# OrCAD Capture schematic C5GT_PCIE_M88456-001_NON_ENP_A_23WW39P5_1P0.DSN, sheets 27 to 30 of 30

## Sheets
27 Power 5 - 1.5V: size B
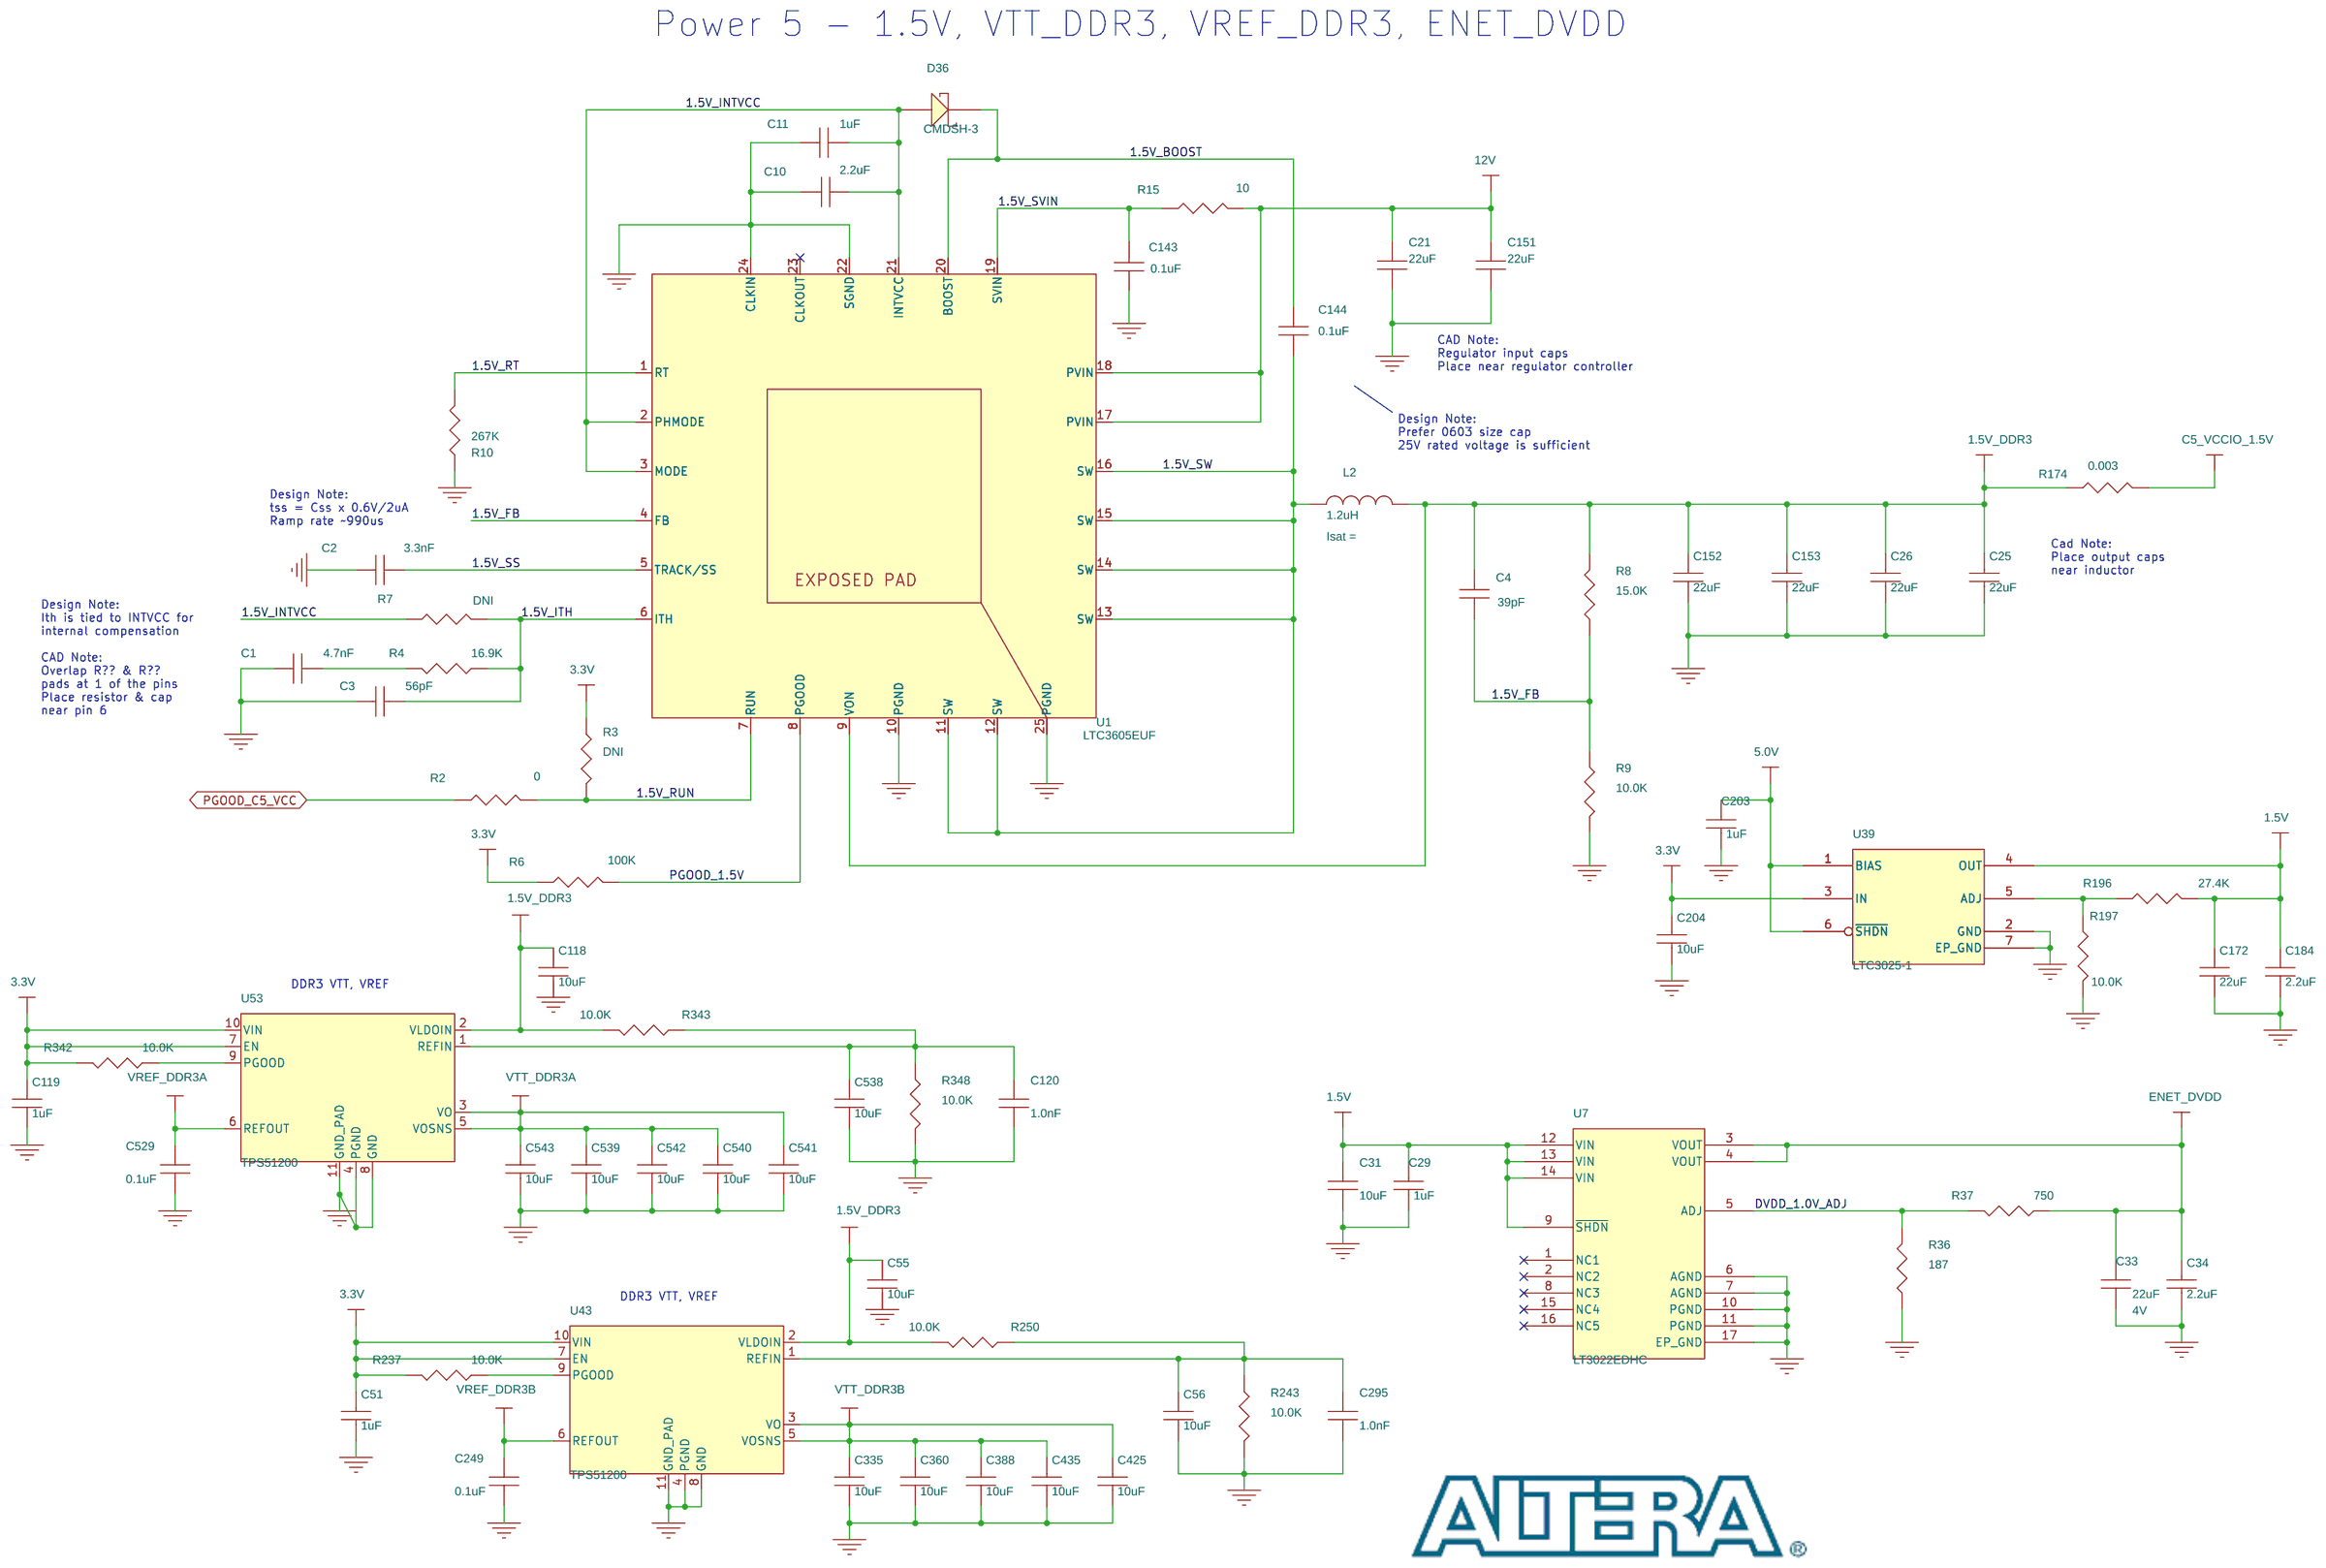
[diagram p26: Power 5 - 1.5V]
28 Power 6 - LTC3605 VAR: size B
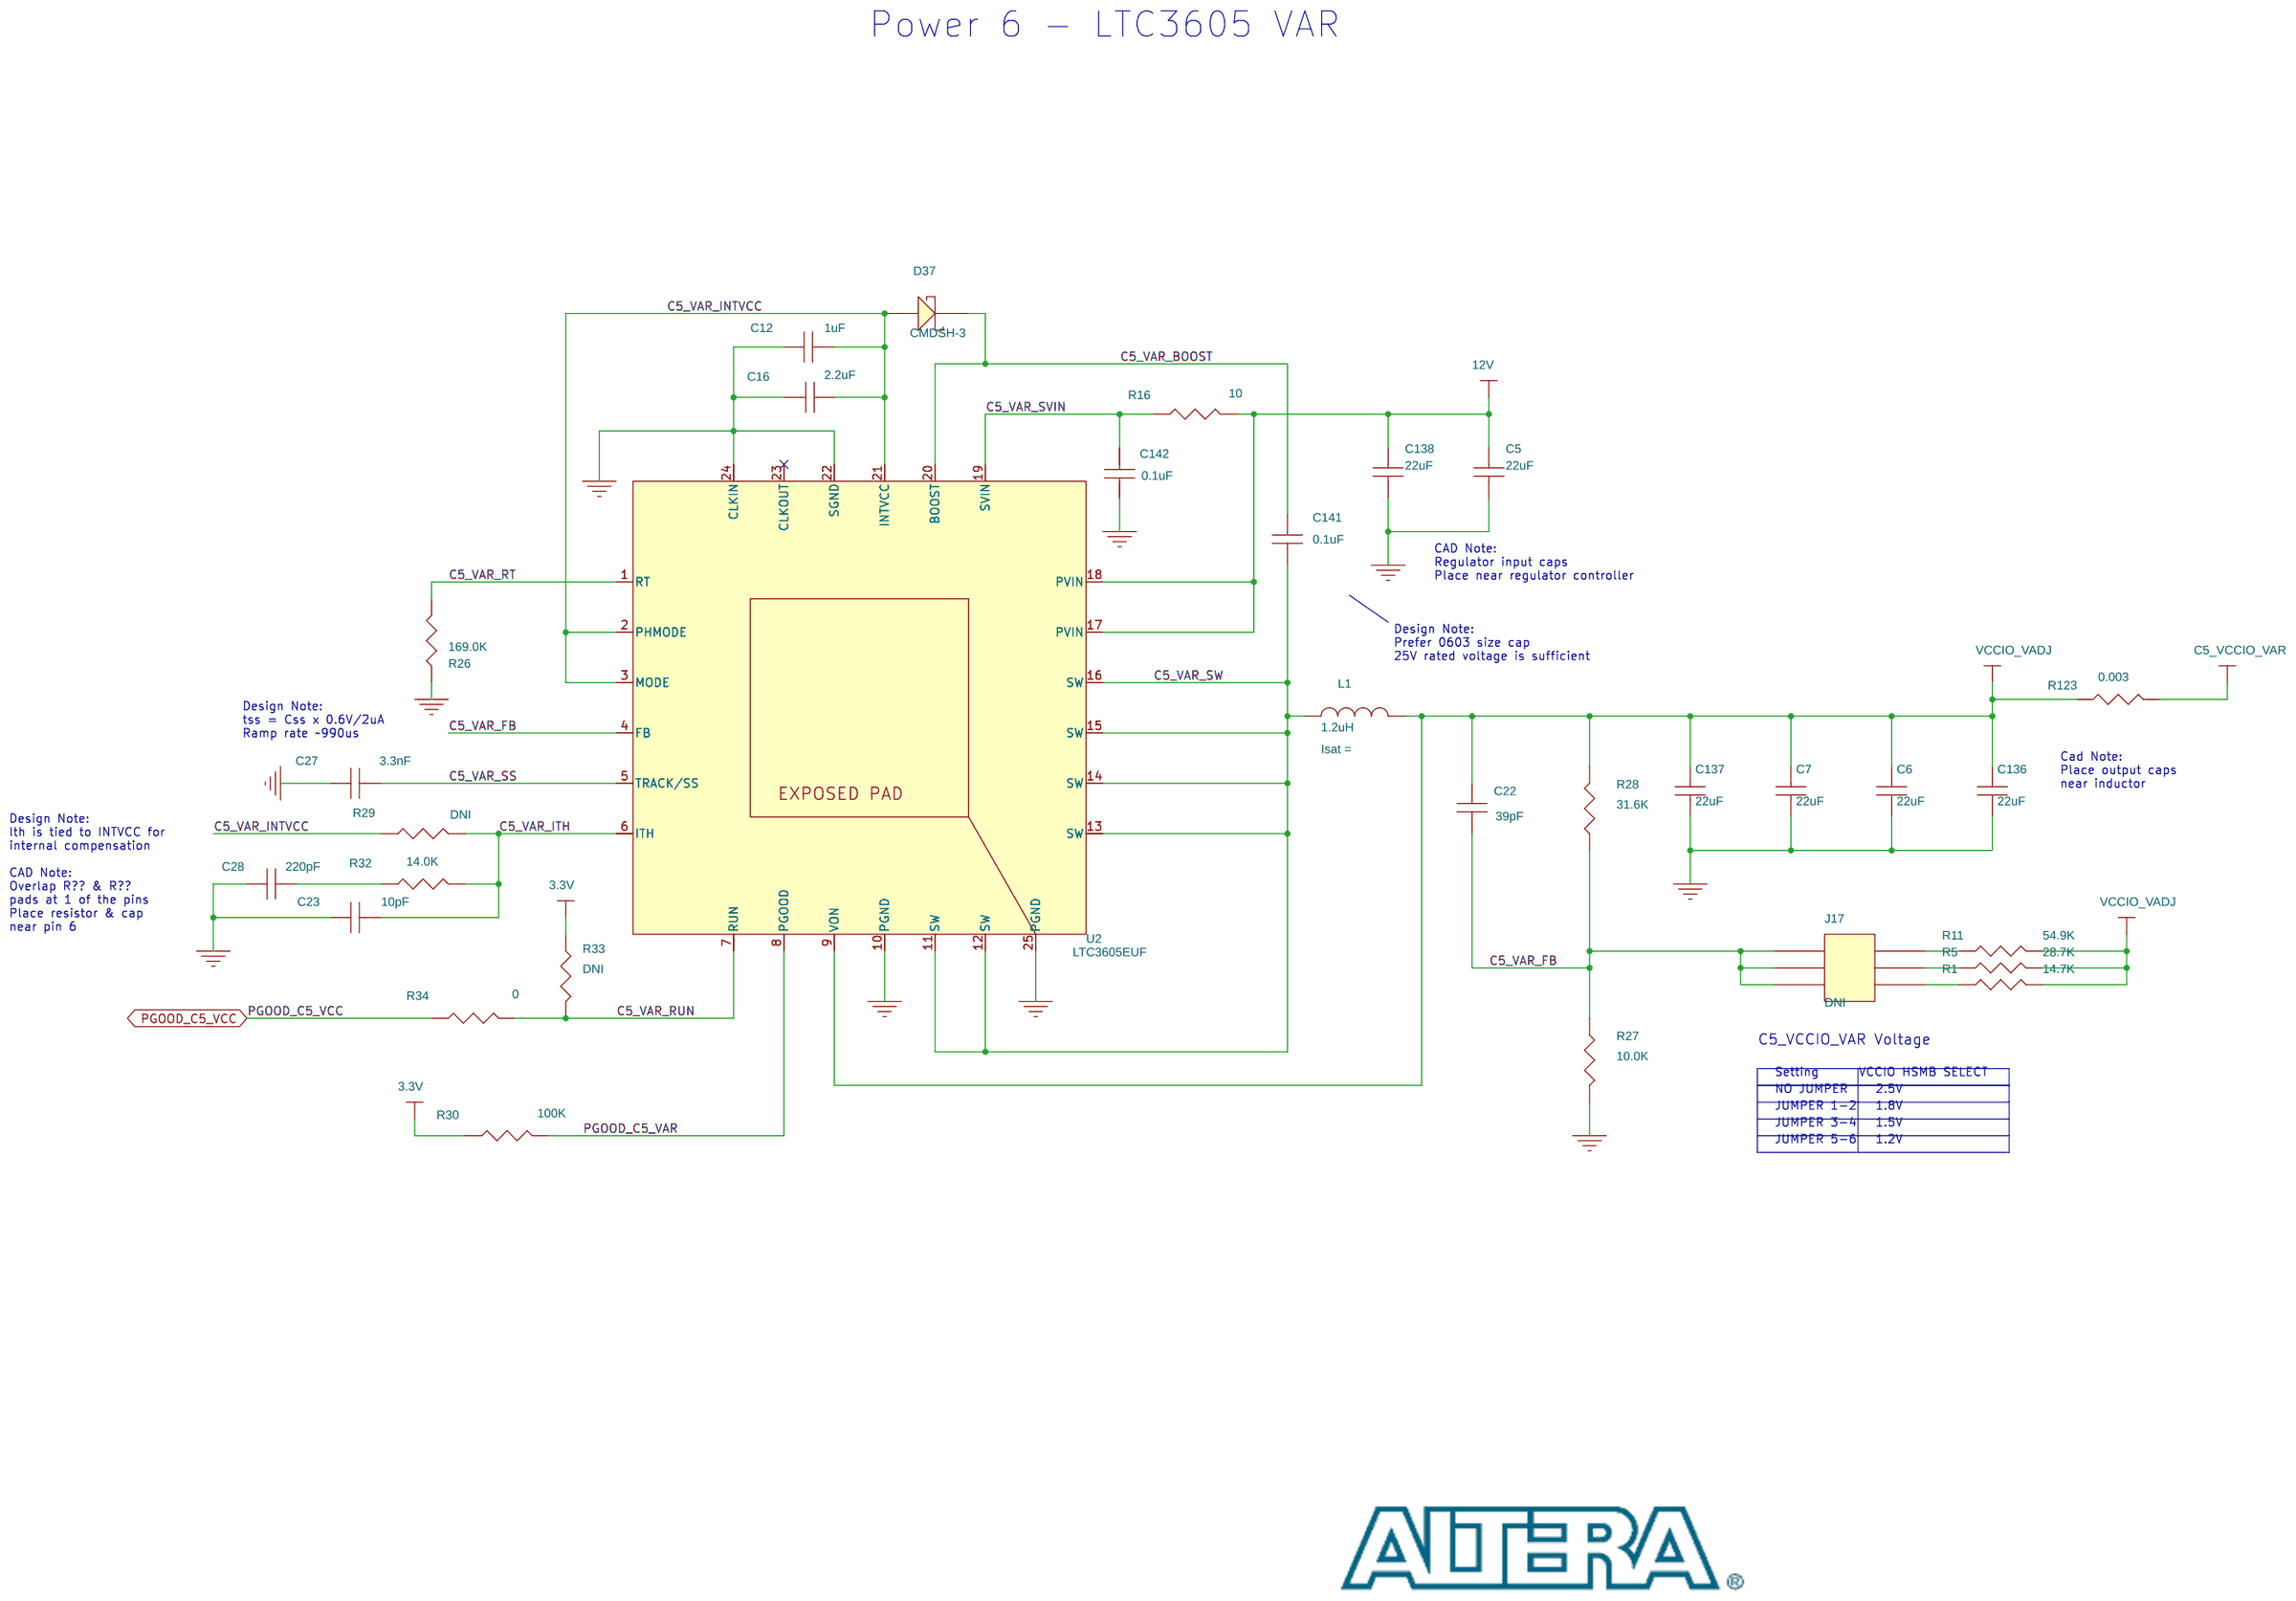
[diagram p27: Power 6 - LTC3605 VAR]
29 Power 7 - Power Monitor: size B
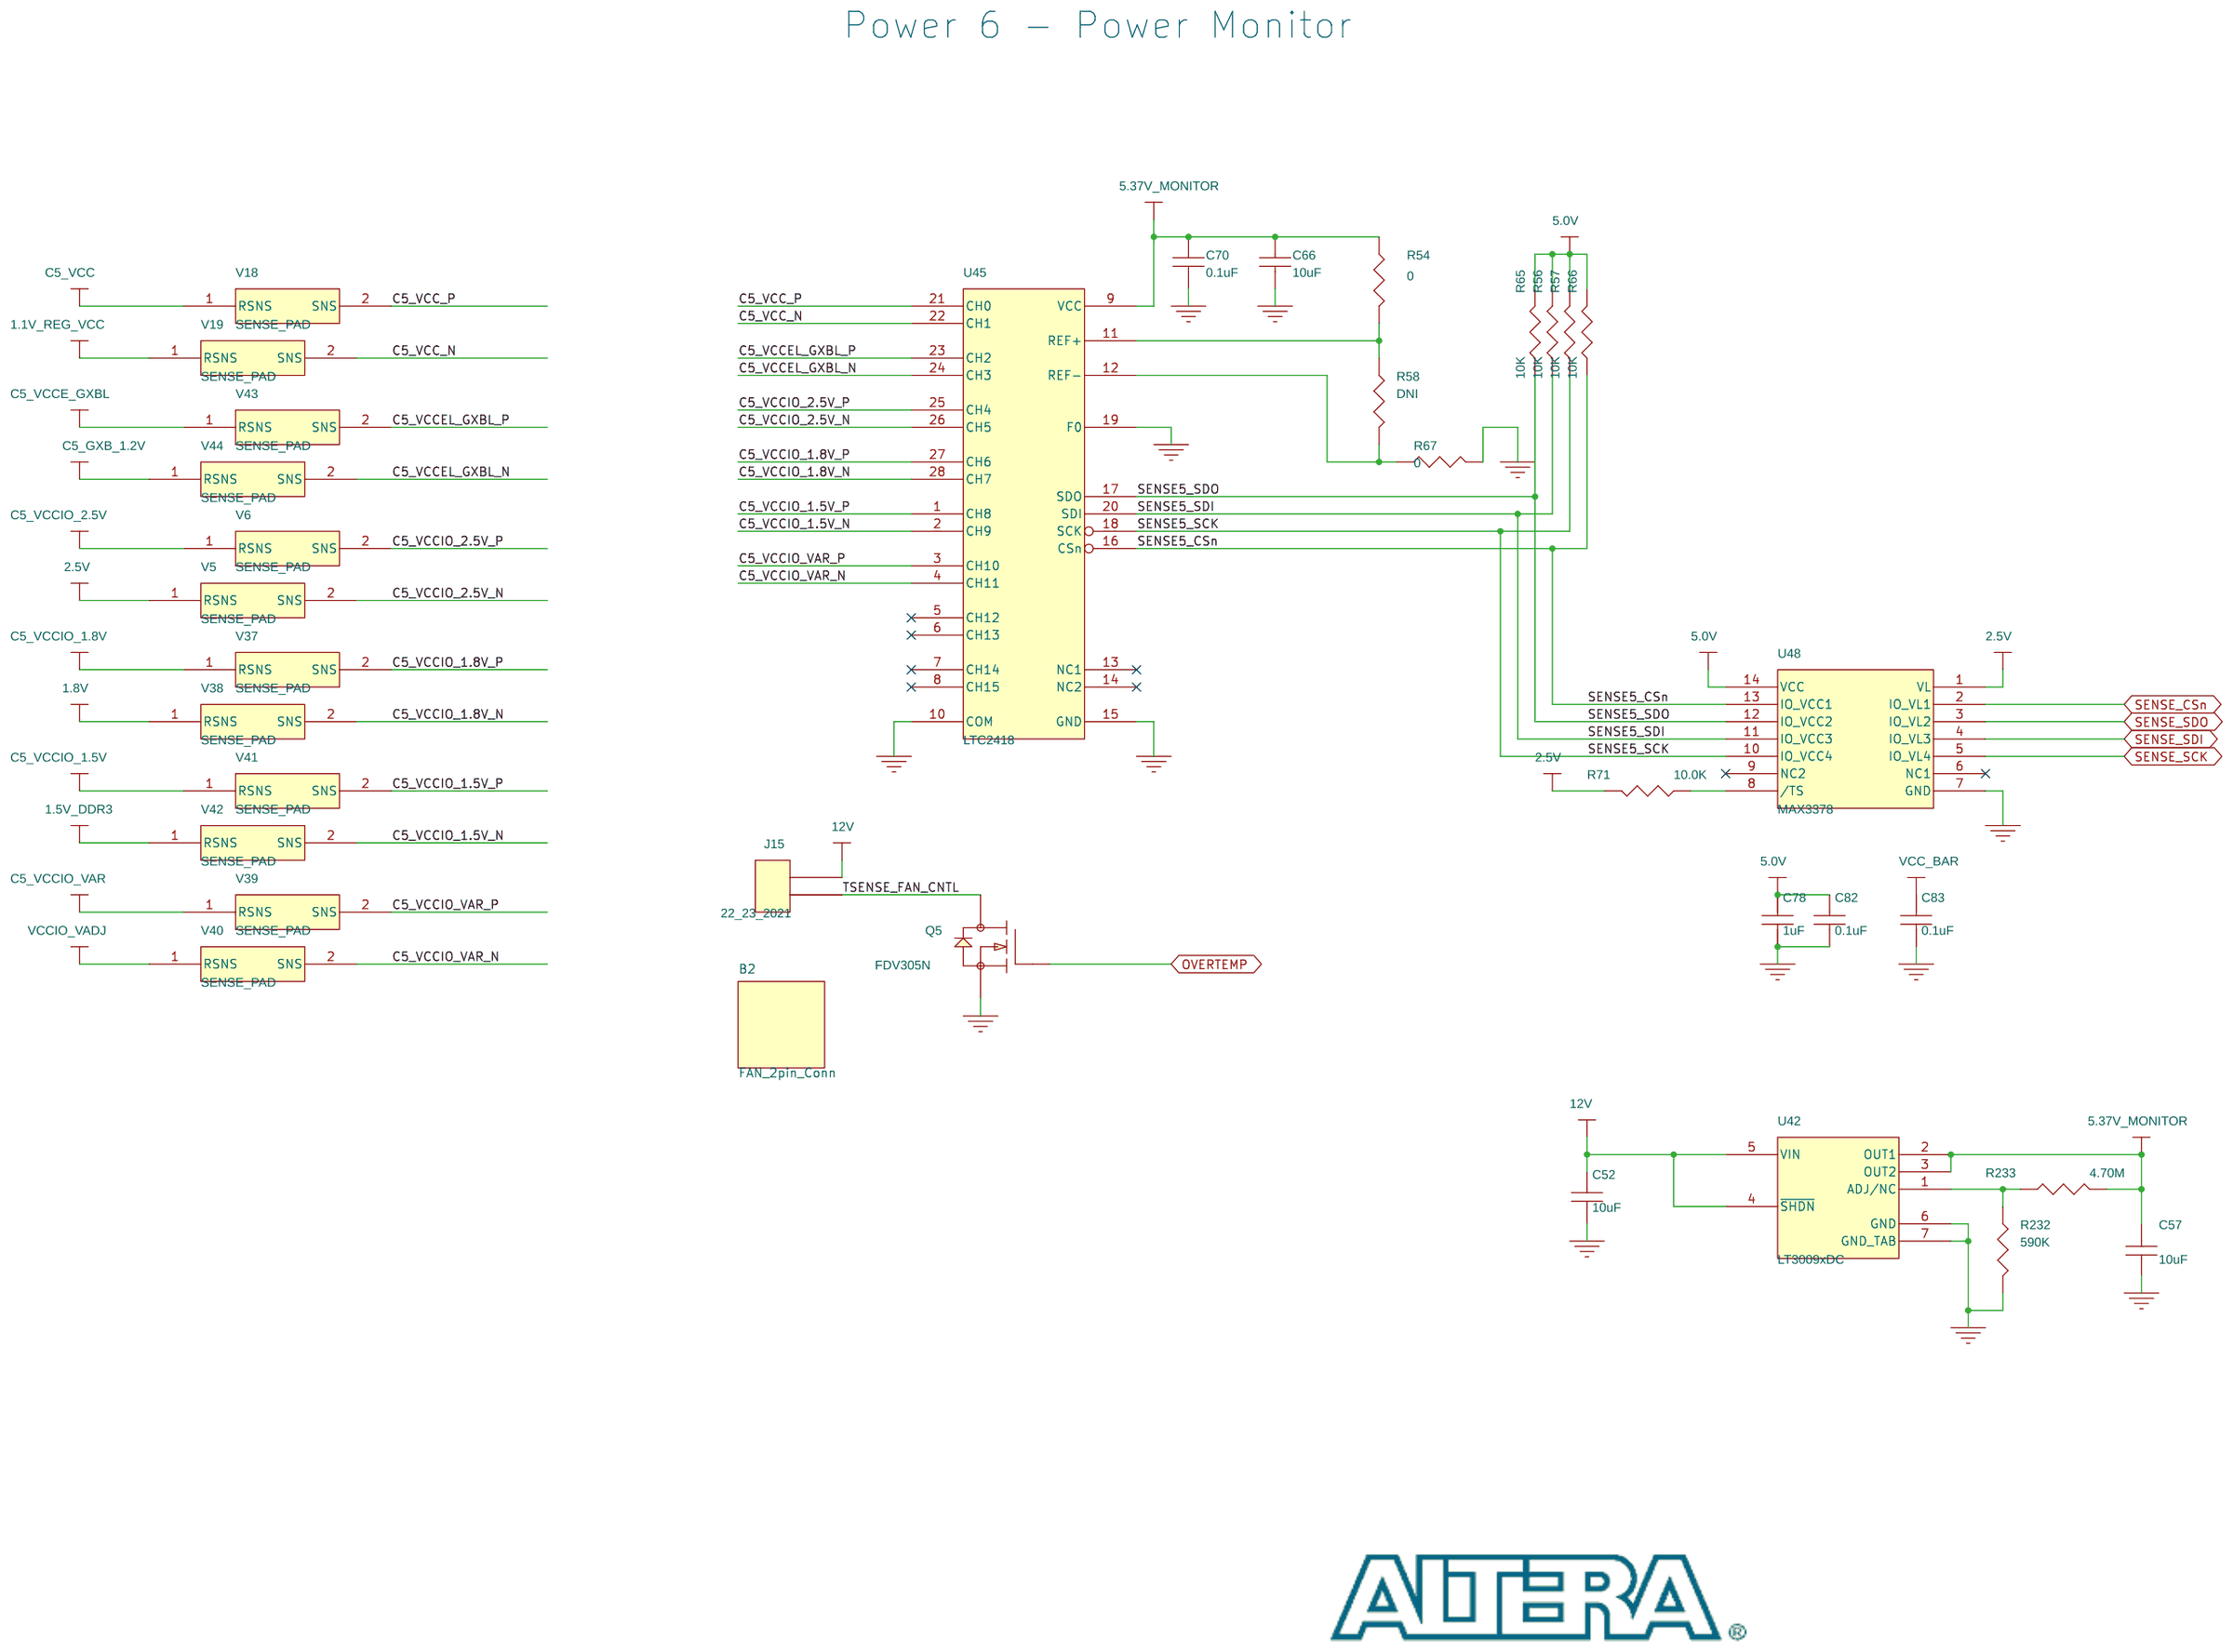
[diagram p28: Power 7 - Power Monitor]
30 Cyclone V GT Decoupling: size B
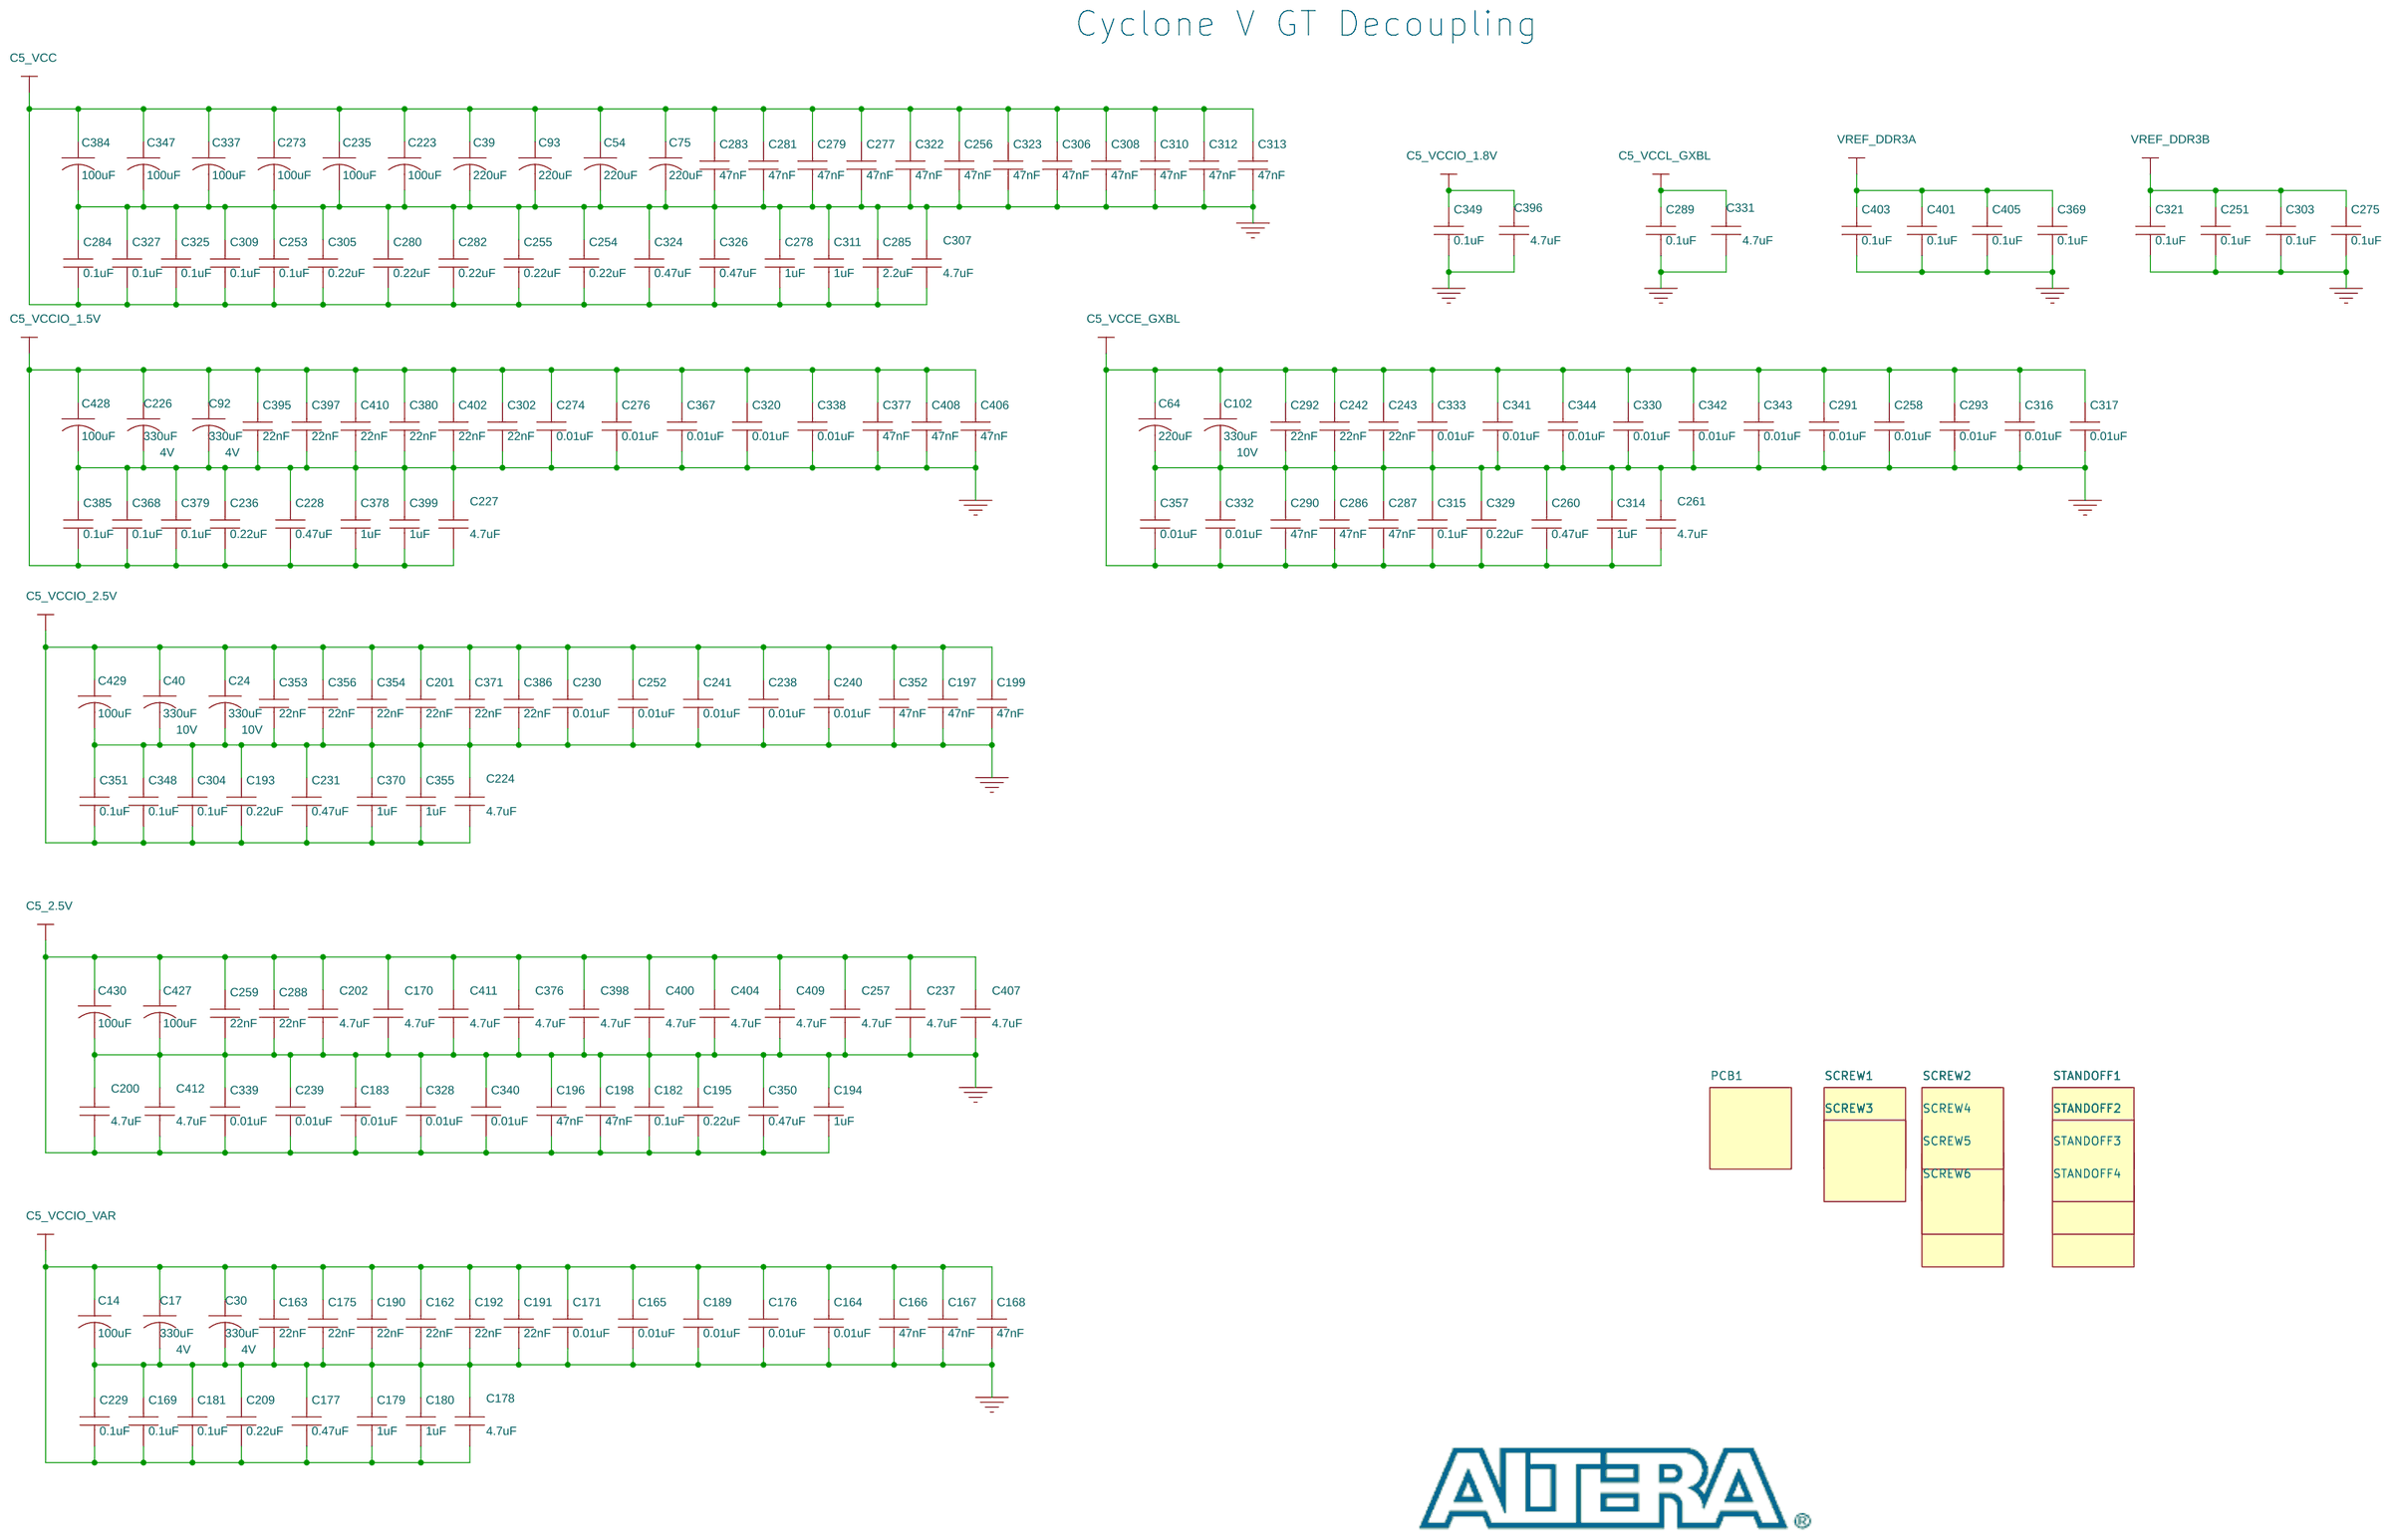
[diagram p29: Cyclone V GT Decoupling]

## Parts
sheet Cyclone V GT Decoupling
C14  100uF  [Avx-1210_case-b]
C17  330uF  [7343-V_low-profile]
C24  330uF  [7343p]
C30  330uF  [7343-V_low-profile]
C39  220uF  [7343P]
C40  330uF  [7343p]
C54  220uF  [7343P]
C64  220uF  [7343P]
C75  220uF  [7343P]
C92  330uF  [7343-V_low-profile]
C93  220uF  [7343P]
C102  330uF  [7343p]
C162  22nF  [0402]
C163  22nF  [0402]
C164  0.01uF  [0402]
C165  0.01uF  [0402]
C166  47nF  [0402]
C167  47nF  [0402]
C168  47nF  [0402]
C169  0.1uF  [0402]
C170  4.7uF  [0402]
C171  0.01uF  [0402]
C175  22nF  [0402]
C176  0.01uF  [0402]
C177  0.47uF  [0402]
C178  4.7uF  [0402]
C179  1uF  [0402]
C180  1uF  [0402]
C181  0.1uF  [0402]
C182  0.1uF  [0402]
C183  0.01uF  [0402]
C189  0.01uF  [0402]
C190  22nF  [0402]
C191  22nF  [0402]
C192  22nF  [0402]
C193  0.22uF  [0402]
C194  1uF  [0402]
C195  0.22uF  [0402]
C196  47nF  [0402]
C197  47nF  [0402]
C198  47nF  [0402]
C199  47nF  [0402]
C200  4.7uF  [0402]
C201  22nF  [0402]
C202  4.7uF  [0402]
C209  0.22uF  [0402]
C223  100uF  [Avx-1210_case-b]
C224  4.7uF  [0402]
C226  330uF  [7343-V_low-profile]
C227  4.7uF  [0402]
C228  0.47uF  [0402]
C229  0.1uF  [0402]
C230  0.01uF  [0402]
C231  0.47uF  [0402]
C235  100uF  [Avx-1210_case-b]
C236  0.22uF  [0402]
C237  4.7uF  [0402]
C238  0.01uF  [0402]
C239  0.01uF  [0402]
C240  0.01uF  [0402]
C241  0.01uF  [0402]
C242  22nF  [0402]
C243  22nF  [0402]
C251  0.1uF  [0402]
C252  0.01uF  [0402]
C253  0.1uF  [0402]
C254  0.22uF  [0402]
C255  0.22uF  [0402]
C256  47nF  [0402]
C257  4.7uF  [0402]
C258  0.01uF  [0402]
C259  22nF  [0402]
C260  0.47uF  [0402]
C261  4.7uF  [0402]
C273  100uF  [Avx-1210_case-b]
C274  0.01uF  [0402]
C275  0.1uF  [0402]
C276  0.01uF  [0402]
C277  47nF  [0402]
C278  1uF  [0402]
C279  47nF  [0402]
C280  0.22uF  [0402]
C281  47nF  [0402]
C282  0.22uF  [0402]
C283  47nF  [0402]
C284  0.1uF  [0402]
C285  2.2uF  [0402]
C286  47nF  [0402]
C287  47nF  [0402]
C288  22nF  [0402]
C289  0.1uF  [0402]
C290  47nF  [0402]
C291  0.01uF  [0402]
C292  22nF  [0402]
C293  0.01uF  [0402]
C302  22nF  [0402]
C303  0.1uF  [0402]
C304  0.1uF  [0402]
C305  0.22uF  [0402]
C306  47nF  [0402]
C307  4.7uF  [0402]
C308  47nF  [0402]
C309  0.1uF  [0402]
C310  47nF  [0402]
C311  1uF  [0402]
C312  47nF  [0402]
C313  47nF  [0402]
C314  1uF  [0402]
C315  0.1uF  [0402]
C316  0.01uF  [0402]
C317  0.01uF  [0402]
C320  0.01uF  [0402]
C321  0.1uF  [0402]
C322  47nF  [0402]
C323  47nF  [0402]
C324  0.47uF  [0402]
C325  0.1uF  [0402]
C326  0.47uF  [0402]
C327  0.1uF  [0402]
C328  0.01uF  [0402]
C329  0.22uF  [0402]
C330  0.01uF  [0402]
C331  4.7uF  [0402]
C332  0.01uF  [0402]
C333  0.01uF  [0402]
C337  100uF  [Avx-1210_case-b]
C338  0.01uF  [0402]
C339  0.01uF  [0402]
C340  0.01uF  [0402]
C341  0.01uF  [0402]
C342  0.01uF  [0402]
C343  0.01uF  [0402]
C344  0.01uF  [0402]
C347  100uF  [Avx-1210_case-b]
C348  0.1uF  [0402]
C349  0.1uF  [0402]
C350  0.47uF  [0402]
C351  0.1uF  [0402]
C352  47nF  [0402]
C353  22nF  [0402]
C354  22nF  [0402]
C355  1uF  [0402]
C356  22nF  [0402]
C357  0.01uF  [0402]
C367  0.01uF  [0402]
C368  0.1uF  [0402]
C369  0.1uF  [0402]
C370  1uF  [0402]
C371  22nF  [0402]
C376  4.7uF  [0402]
C377  47nF  [0402]
C378  1uF  [0402]
C379  0.1uF  [0402]
C380  22nF  [0402]
C384  100uF  [Avx-1210_case-b]
C385  0.1uF  [0402]
C386  22nF  [0402]
C395  22nF  [0402]
C396  4.7uF  [0402]
C397  22nF  [0402]
C398  4.7uF  [0402]
C399  1uF  [0402]
C400  4.7uF  [0402]
C401  0.1uF  [0402]
C402  22nF  [0402]
C403  0.1uF  [0402]
C404  4.7uF  [0402]
C405  0.1uF  [0402]
C406  47nF  [0402]
C407  4.7uF  [0402]
C408  47nF  [0402]
C409  4.7uF  [0402]
C410  22nF  [0402]
C411  4.7uF  [0402]
C412  4.7uF  [0402]
C427  100uF  [Avx-1210_case-b]
C428  100uF  [Avx-1210_case-b]
C429  100uF  [Avx-1210_case-b]
C430  100uF  [Avx-1210_case-b]
PCB1  PCB FAB
SCREW1  SCREW
SCREW2  SCREW
SCREW3  SCREW
SCREW4  SCREW
SCREW5  SCREW
SCREW6  SCREW
STANDOFF1  STANDOFF
STANDOFF2  STANDOFF
STANDOFF3  STANDOFF
STANDOFF4  STANDOFF
sheet Power 5 - 1.5V
C1  4.7nF  [0402]
C2  3.3nF  [0402]
C3  56pF  [0402]
C4  39pF  [0402]
C10  2.2uF  [0402]
C11  1uF  [0603]
C21  22uF  [1210]
C25  22uF  [0805]
C26  22uF  [0805]
C29  1uF  [0402]
C31  10uF  [0603]
C33  22uF  [0603]
C34  2.2uF  [0603]
C51  1uF  [0402]
C55  10uF  [0603]
C56  10uF  [0603]
C118  10uF  [0603]
C119  1uF  [0402]
C120  1.0nF  [0402]
C143  0.1uF  [0402]
C144  0.1uF  [0603]
C151  22uF  [1210]
C152  22uF  [0805]
C153  22uF  [0805]
C172  22uF  [1210]
C184  2.2uF  [0603]
C203  1uF  [0402]
C204  10uF  [0805]
C249  0.1uF  [0402]
C295  1.0nF  [0402]
C335  10uF  [0603]
C360  10uF  [0603]
C388  10uF  [0603]
C425  10uF  [0603]
C435  10uF  [0603]
C529  0.1uF  [0402]
C538  10uF  [0603]
C539  10uF  [0603]
C540  10uF  [0603]
C541  10uF  [0603]
C542  10uF  [0603]
C543  10uF  [0603]
D36  CMDSH-3  [SOD323]
L2  1.2uH  [IND_SUSUMU_PCMC_BTYPE]
R2  0  [0402]
R3  DNI  [0402]
R4  16.9K  [0402]
R6  100K  [0402]
R7  DNI  [0402]
R8  15.0K  [0402]
R9  10.0K  [0402]
R10  267K  [0402]
R15  10  [0402]
R36  187  [0402]
R37  750  [0402]
R174  0.003  [WSL2010]
R196  27.4K  [0402]
R197  10.0K  [0402]
R237  10.0K  [0402]
R243  10.0K  [0402]
R250  10.0K  [0402]
R342  10.0K  [0402]
R343  10.0K  [0402]
R348  10.0K  [0402]
U1  LTC3605EUF  [qfn24]
U7  LT3022EDHC  [dfn16_epad_5x3]
U39  LTC3025-1  [DFN6-2x2_EPAD]
U43  TPS51200  [DRC-10_epad]
U53  TPS51200  [DRC-10_epad]
sheet Power 6 - LTC3605 VAR
C5  22uF  [1210]
C6  22uF  [0805]
C7  22uF  [0805]
C12  1uF  [0603]
C16  2.2uF  [0402]
C22  39pF  [0402]
C23  10pF  [0402]
C27  3.3nF  [0402]
C28  220pF  [0402]
C136  22uF  [0805]
C137  22uF  [0805]
C138  22uF  [1210]
C141  0.1uF  [0603]
C142  0.1uF  [0402]
D37  CMDSH-3  [SOD323]
J17  DNI  [SAMTEC_HDR_2X3_2MM_SMT]
L1  1.2uH  [IND_SUSUMU_PCMC_BTYPE]
R1  14.7K  [0402]
R5  28.7K  [0402]
R11  54.9K  [0402]
R16  10  [0402]
R26  169.0K  [0402]
R27  10.0K  [0402]
R28  31.6K  [0402]
R29  DNI  [0402]
R30  100K  [0402]
R32  14.0K  [0402]
R33  DNI  [0402]
R34  0  [0402]
R123  0.003  [WSL2010]
U2  LTC3605EUF  [qfn24]
sheet Power 7 - Power Monitor
B2  FAN_2pin_Conn
C52  10uF  [1206]
C57  10uF  [0603]
C66  10uF  [0805]
C70  0.1uF  [0402]
C78  1uF  [0402]
C82  0.1uF  [0402]
C83  0.1uF  [0402]
J15  22_23_2021  [MLX_22_23_2021_VRT_HDR_2P]
Q5  FDV305N  [SOT23]
R54  0  [0402]
R56  10K  [0402]
R57  10K  [0402]
R58  DNI  [0402]
R65  10K  [0402]
R66  10K  [0402]
R67  0  [0402]
R71  10.0K  [0402]
R232  590K  [0402]
R233  4.70M  [0402]
U42  LT3009xDC  [DFN6-2X2_EPAD]
U45  LTC2418  [ssop28_nar]
U48  MAX3378  [TSSOP14]
V5  SENSE_PAD  [SENSE]
V6  SENSE_PAD  [SENSE]
V18  SENSE_PAD  [SENSE]
V19  SENSE_PAD  [SENSE]
V37  SENSE_PAD  [SENSE]
V38  SENSE_PAD  [SENSE]
V39  SENSE_PAD  [SENSE]
V40  SENSE_PAD  [SENSE]
V41  SENSE_PAD  [SENSE]
V42  SENSE_PAD  [SENSE]
V43  SENSE_PAD  [SENSE]
V44  SENSE_PAD  [SENSE]

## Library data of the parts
C14 C223 C235 C273 C337 C347 C384 C427-C430 = PCAP: CAP - TANT, 100UF, 6.3V, 20%, ESR 0.045 OHM, POLY SMD; AGILE_LINK: http://sj-agile9app/Agile/PLMServlet?action=OpenEmailObject&classid=10000&objid=257237054; IPN: K16360-001; Item Num: P03-17352R; LIFECYCLE_PHASE: Active; Lead Free Status: Lead Free; MFR_LIFECYCLE: Active; Manufacturer: AVX Corp; Manufacturer Part Num: TCJB107M006R0045; Num Pins: 2; PART_SUBCLASS: CAPACITORS; RATED_VOLTAGE: 6.3V; RoHS Compliant: RoHS Compliant; TOLERANCE: +/-20%
C17 C30 C92 C226 = PCAP: CAP - TANT, 330uF, 20%, 4V, 40mOhm ESR, SMD Low-profile (1.9mm); IPN: 724613-057; Item Num: P03-17473R; LIFECYCLE_PHASE: Active; Lead Free Status: Lead Free; MFR_LIFECYCLE: Active; Manufacturer: Kemet; Manufacturer Part Num: T520V337M004ATE040; Num Pins: 2; PART_SUBCLASS: CAPACITORS; RATED_VOLTAGE: 4V; RoHS Compliant: RoHS Compliant; TOLERANCE: +/-20%
C24 C40 C102 = PCAP: CAP - TANT, 330UF, 10V, 20%, SMD; AGILE_LINK: http://sj-agile9app/Agile/PLMServlet?action=OpenEmailObject&classid=10000&objid=257237054; IPN: K16359-001; Item Num: P03-15278R; LIFECYCLE_PHASE: Active; Lead Free Status: Lead Free; MFR_LIFECYCLE: Active; Manufacturer: AVX Corp; Manufacturer Part Num: TPME337M010R0023; Num Pins: 2; PART_SUBCLASS: CAPACITORS; RATED_VOLTAGE: 10V; RoHS Compliant: RoHS Compliant; TOLERANCE: +/-20%
C39 C54 C64 C75 C93 = PCAP: CAP - TANT, 220UF, 20%, 6.3VDC, 25mOhm ESR; IPN: N13712-001; Item Num: P03-17629R; LIFECYCLE_PHASE: Active; Lead Free Status: Lead Free; MFR_LIFECYCLE: Active; Manufacturer: Kemet; Manufacturer Part Num: T520V227M006ZTE025; Num Pins: 2; PART_SUBCLASS: CAPACITORS; RATED_VOLTAGE: 6.3V; RoHS Compliant: RoHS Compliant; TOLERANCE: +/-20%
C162 C163 C175 C190-C192 C201 C242 C243 C259 C288 C292 C302 C353 C354 C356 C371 C380 C386 C395 C397 C402 C410 = CAP: CAP - CER, 22NF, 25V, +/-10%, X7R, 0402 SMD; AGILE_LINK: http://sj-agile9app/Agile/PLMServlet?action=OpenEmailObject&classid=10000&objid=256989767; CAPACITANCE: 22000pF; IPN: A36096-089; Item Num: P03-16317R; LIFECYCLE_PHASE: Active; Lead Free Status: Lead Free; MFR_LIFECYCLE: Active; Manufacturer: Murata; Manufacturer Part Num: GRM155R71E223KA61D; Num Pins: 2; PART_SUBCLASS: CAPACITORS; RATED_VOLTAGE: 25V; RoHS Compliant: RoHS Compliant; TOLERANCE: +80%/-20%
C164 C165 C171 C176 C183 C189 C230 C238-C241 C252 C258 C274 C276 C291 C293 C316 C317 C320 C328 C330 C332 C333 C338-C344 C357 C367 = CAP: CAP - CER, 10NF, 50V, +/-10%, X7R, 0402 SMD; Dielectric: X5R; IPN: H61346-001; Item Num: P03-16318R; Lead Free Status: Yes; Manufacturer: Murata; Manufacturer Part Num: GRM155R71H103KA88D; Manufacturer's Part No.: GRM155R71H103KA88D; Num Pins: 2; Part Class: CAPACITORS; Price: 0.07; RoHS Compliant: Yes; Tolerance: 10%
C166-C168 C196-C199 C256 C277 C279 C281 C283 C286 C287 C290 C306 C308 C310 C312 C313 C322 C323 C352 C377 C406 C408 = CAP: CAP - CER, 47000PF, 25V, X7R, 0402; IPN: K13558-001; Item Num: P03-15073R; Lead Free Status: Yes; Manufacturer: Murata; Manufacturer Part Num: GRM155R71E473KA88D; Num Pins: 2; Part Class: Capacitors; Price: 0; RoHS Compliant: Yes; Supplier Part Num: GRM155R71E473KA88D
C82 C83 C169 C181 C182 C229 C249 C251 C253 C275 C284 C289 C303 C304 C309 C315 C321 C325 C327 C348 C349 C351 C368 C369 C379 C385 C401 C403 C405 C529 = CAP: CAP - CERAMIC,  0.1UF 0402 25VDC Y5V; Dielectric: X5R; IPN: K13560-001; Item Num: P03-15057R; LIFECYCLE_PHASE: Active; Lead Free Status: Lead Free; Manufacturer: Murata; Manufacturer Part Num: GRM155F51E104ZA01D; Num Pins: 2; Part Class: CAPACITORS; Price: 0.07; RoHS Compliant: RoHS Compliant; Tolerance: +80%/-20%
C170 C178 C200 C202 C224 C227 C237 C257 C261 C307 C331 C376 C396 C398 C400 C404 C407 C409 C411 C412 = CAP: CAP - CERAMIC, 4.7UF, 6.3V, 10%, X5R, 0402; AGILE_LINK: http://sj-agile9app/Agile/PLMServlet?action=OpenEmailObject&classid=10000&objid=257560276; IPN: A36096-107; Item Num: P03-17432R; LIFECYCLE_PHASE: Active; Lead Free Status: Not Lead Free; MFR_LIFECYCLE: Active; Manufacturer: Murata; Manufacturer Part Num: GRM155R60J475ME87D; Num Pins: 2; PART_SUBCLASS: CAPACITORS; RATED_VOLTAGE: 6.3V; RoHS Compliant: RoHS Compliant; TOLERANCE: +/-10%
C177 C228 C231 C260 C324 C326 C350 = CAP: CAP - CER, .47UF, 10V, X5R, 0402; Dielectric: X5R; IPN: A36096-119; Item Num: P03-15085R; LIFECYCLE_PHASE: Active; Lead Free Status: Lead Free; Manufacturer: Murata; Manufacturer Part Num: GRM155R61A474KE15D; Num Pins: 2; Part Class: CAPACITORS; RoHS Compliant: RoHS Compliant; Tolerance: +80%/-20%
C78 C179 C180 C194 C278 C311 C314 C355 C370 C378 C399 = CAP: CAP - CER, 1UF, 10V, +/-10%, X5R, 0402; AGILE_LINK: http://sj-agile9app/Agile/PLMServlet?action=OpenEmailObject&classid=10000&objid=256999866; IPN: A36096-099; Item Num: P03-15479R; LIFECYCLE_PHASE: Active; Lead Free Status: Lead Free; MFR_LIFECYCLE: Active; Manufacturer: Murata; Manufacturer Part Num: GRM155R61A105KE15D; Num Pins: 2; PART_SUBCLASS: CAPACITORS; RATED_VOLTAGE: 10V; RoHS Compliant: RoHS Compliant; TOLERANCE: +/-10%
C193 C195 C209 C236 C254 C255 C280 C282 C305 C329 = CAP: CAP - CERAMIC, 0.22UF, 10V, X5R, 10%, 0402; AGILE_LINK: http://sj-agile9app/Agile/PLMServlet?action=OpenEmailObject&classid=10000&objid=257560276; IPN: A36096-078; Item Num: P03-15149R; LIFECYCLE_PHASE: Active; Lead Free Status: Not Lead Free; MFR_LIFECYCLE: Active; Manufacturer: Murata; Manufacturer Part Num: GRM155R61A224KE19D; Num Pins: 2; PART_SUBCLASS: CAPACITORS; RATED_VOLTAGE: 10V; RoHS Compliant: RoHS Compliant; TOLERANCE: +/-10%
C285 = CAP: CAP - 2.2UF, 20%, X5R 6.3VDC, 0402, LOW ESR; Dielectric: X5R; IPN: H68861-001; Item Num: P03-17314R; Lead Free Status: Yes; Manufacturer: TDK Electronics; Manufacturer Part Num: C1005X5R0J225M; Manufacturer's Part No.: C1005X5R0J225M; Num Pins: 2; Part Class: CAPACITORS; Price: 0.07; RoHS Compliant: Yes; Tolerance: 10%
PCB1 = BLANK_PART: RAW PCB FAB, CYCLONE V GT DEV KIT BOARD (6XX-44179R) REV B; Item Num: P06-21513R; Manufacturer: TTM Technologies; Manufacturer Part Num: 100-0321004-b1
SCREW1 SCREW3 = BLANK_PART: FASTNERS/MACHINE SCREW, 4-40 THREAD, 1/4", PHILLIPS PANHEAD; IPN: K14329-001; Item Num: P12-11696R; Manufacturer: Building Fasteners; Manufacturer Part Num: PMSSS 440 0025 PH
SCREW2 SCREW4-SCREW6 = BLANK_PART: HARDWARE SCREW STAINLESS STEEL PHILLIPS PANHEAD 4-40 9.5MM; IPN: K14324-001; Item Num: P12-25024R; Manufacturer: Building Fasteners; Manufacturer Part Num: PMSSS 440 0038 PH
STANDOFF1-STANDOFF4 = BLANK_PART: HARDWARE STANDOFF 1" HEX 4-40 THREADED BRASS ZINC PLATED O.D. 0.187"; IPN: K14330-001; Item Num: P12-25023R; Manufacturer: Keystone Electronics Corporation; Manufacturer Part Num: 1656B
C1 = CAP: CAP - CER 4700PF 50V 10% X7R 0402; AGILE_LINK: http://sj-agile9app/Agile/PLMServlet?action=OpenEmailObject&classid=10000&objid=215384813; IPN: A36096-066; Item Num: P03-15074R; LIFECYCLE_PHASE: Active; Lead Free Status: Lead Free; MFR_LIFECYCLE: Active; Manufacturer: Murata; Manufacturer Part Num: GRM155R71H472KA01D; Num Pins: 2; PACKAGING: Tape & Reel (TR); PART_SUBCLASS: CAPACITORS; RATED_VOLTAGE: 50V; RoHS Compliant: RoHS Compliant; Supplier Part Num: GRM155R71H472KA01D; Tolerance: +/-10%
C2 C27 = Cap_3300PF_10%_50V_0402: CAP, CERAMIC, 3300PF, 10%, 50V, X7R, 0402; IPN: K13754-001; Manufacturer: Murata; Manufacturer Part Num: GRM155F51H332ZA01x
C3 = CAP: CAP - CER, 56pF, 5%, 50VDC, NPO, 0402; IPN: H61343-001; Item Num: P03-17589R; Manufacturer: Kemet; Manufacturer Part Num: C0402C560J5GACTU; Num Pins: 2; PART_SUBCLASS: CAPACITORS
C4 C22 = Cap_39PF_5%_50V_0402: IPN: A36095-021
C10 C16 = Cap_2.2uF_+_-20%_6.3V_0402: IPN: H68861-001
C11 C12 = Cap_1.0UF_10%_6.3V_0603: IPN: H86538-001; Manufacturer: Panasonic; Manufacturer Part Num: ECJ-1VB0J105K
C5 C21 C138 C151 = CAP_22uF_+_-10%_25V_1210: IPN: G38032-001
C6 C7 C25 C26 C136 C137 C152 C153 = CAP_22uF_+_-10%_6.3V_0805: IPN: K13617-001
C29 C51 C119 C203 = CAP: CAP, CERAMIC, 1UF, 0402, 10%, 10VDC,  X5R; IPN: A36096-099; Item Num: P03-15010R; Lead Free Status: No; Manufacturer: Panasonic; Manufacturer Part Num: ECJ-0EB1A105M; Num Pins: 2; Part Class: Capacitors; Price: 0; RoHS Compliant: Yes
C31 C57 = CAP: CAP - CER 10UF 6.3V 20% X5R 0603; IPN: K13611-001; Item Num: P03-15733R; Lead Free Status: Yes; Manufacturer: Murata; Manufacturer Part Num: GRM188R60J106ME47X; Manufacturer's Part No.: GRM188R60J106ME47X; Num Pins: 2; Part Class: CAPACITORS; RoHS Compliant: Yes
C33 = CAP: CAP - CER, 22UF, 4V, X5R, 0603, SMD; IPN: H83244-001; Item Num: P03-17412R; Manufacturer: Murata; Manufacturer Part Num: GRM188R60G226MEA0L; Num Pins: 2; Part Class: Capacitors; RATED_VOLTAGE: 4V; RoHS Compliant: Yes; Tolerance: 20%; Working Voltage: 4V
C34 C184 = CAP: CAP, CERAMIC, 2.2UF, 10%, 10VDC, X5R, 0603; AGILE_LINK: http://sj-agile9app/Agile/PLMServlet?action=OpenEmailObject&classid=10000&objid=256999866; IPN: M97320-001; Item Num: P03-15213R; LIFECYCLE_PHASE: Active; Lead Free Status: Lead Free; MFR_LIFECYCLE: Active; Manufacturer: Murata; Manufacturer Part Num: GRM188R61A225KE34x; Num Pins: 2; PART_SUBCLASS: CAPACITORS; RATED_VOLTAGE: 10V; RoHS Compliant: RoHS Compliant; Supplier Part Num: 490-1545-1-ND; TOLERANCE: +/-10%
C55 C56 C118 C335 C360 C388 C425 C435 C538-C543 = CAP: CAP - CER, 10UF, 6.3V, 20%, X5R, 0603; AGILE_LINK: http://sj-agile9app/Agile/PLMServlet?action=OpenEmailObject&classid=10000&objid=258353688; IPN: G41146-001; Item Num: P03-15792R; LIFECYCLE_PHASE: Active; Lead Free Status: Lead Free; MFR_LIFECYCLE: Active; Manufacturer: Murata; Manufacturer Part Num: GRM188R60J106ME47D; Num Pins: 2; PART_SUBCLASS: CAPACITORS; RATED_VOLTAGE: 6.3V; RoHS Compliant: RoHS Compliant; TOLERANCE: +/-20%
C120 C295 = CAP: CAP - CER, 1NF, 10%, 50V, X7R, 0402; AGILE_LINK: http://sj-agile9app/Agile/PLMServlet?action=OpenEmailObject&classid=10000&objid=256956561; IPN: D62711-001; Item Num: P03-15174R; LIFECYCLE_PHASE: Active; MFR_LIFECYCLE: Active; Manufacturer: Murata; Manufacturer Part Num: GRM155R71H102KA01D; Num Pins: 2; PART_SUBCLASS: CAPACITORS; RATED_VOLTAGE: 50V; RoHS Compliant: RoHS Compliant; TOLERANCE: +/-10%
C142 C143 = Cap_0.1UF_25VDC_0402: CAP - CERAMIC, 0.1UF 0402 25VDC Y5V; IPN: K13560-001
C141 C144 = Cap_0.1UF_50V_0603: IPN: M31986-001; Manufacturer: Panasonic; Manufacturer Part Num: C0603C104K5REC
C172 = CAP: CAP - CERAMIC 22UF 10V X5R 10% 1210; AGILE_LINK: http://sj-agile9app/Agile/PLMServlet?action=OpenEmailObject&classid=10000&objid=216565517; IPN: K13608-001; Item Num: P03-15081R; LIFECYCLE_PHASE: Active; Lead Free Status: Lead Free; MFR_LIFECYCLE: Active; Manufacturer: Murata; Manufacturer Part Num: GRM32ER61A226KE20L; Num Pins: 2; PART_SUBCLASS: CAPACITORS; RATED_VOLTAGE: 10V; RoHS Compliant: RoHS Compliant; TOLERANCE: +/-10%
C204 = CAP: CAP - CERAMIC, 10UF, 10%, 10VDC, 0805, X5R; Dielectric: X7R; IPN: K13557-001; Item Num: P03-15116R; MFR_LIFECYCLE: Active; Manufacturer: Murata; Manufacturer Part Num: GRM21BR61A106KE19L; Num Pins: 2; PART_SUBCLASS: CAPACITORS; Part Class: Capacitors; Price: 0; RoHS Compliant: Yes; Working Voltage: 10V
D36 D37 = DIODE,_SCHOTTKY_CMDSH-3: IPN: A81685-001
L1 L2 = IND_1.2uH_Ir=6.5A_CUBE_SMD: IPN: K14427-001
R2 R7 R29 R34 = RES_0_OHM_5%_1_16W_0402_SMD: IPN: A93549-001
R3 R9 R27 R33 = RES_10.0K_OHM_1.0%_1_16W_0402: IPN: A93548-034
R4 = RESISTOR: RES 16.9K OHM 1/16W 1% 0402 SMD; IPN: K15744-001; Item Num: P02-14035R; Lead Free Status: Yes; Manufacturer: Panasonic; Manufacturer Part Num: ERJ-2RKF1692X; Num Pins: 2; Part Class: Resistors; Price: 0; RoHS Compliant: Yes
R6 R30 = RES_100K_OHM_1.0%_1_16W_0402: IPN: A93548-596
R8 = RESISTOR: RES,15K OHMS,1.0%,1/16W,0402; AGILE_LINK: http://sj-agile9app/Agile/PLMServlet?action=OpenEmailObject&classid=10000&objid=146932246; IPN: A93548-132; Item Num: P02-11397R; LIFECYCLE_PHASE: Active; MFR_LIFECYCLE: Active; Manufacturer: Panasonic; Manufacturer Part Num: ERJ-2RKF1502X; Num Pins: 2; PART_SUBCLASS: RESISTORS; POWER: 1/16W; RESISTANCE: 15K; RoHS Compliant: RoHS Compliant; TOLERANCE: +/-1%
R10 = RESISTOR: RES - 267K OHM, 1/10W, 1%, 0402 SMD; IPN: K15862-001; Item Num: P02-17525R; Manufacturer: Panasonic; Manufacturer Part Num: ERJ-2RKF2673X
R15 R16 = RES_10_OHM_1.0%_1_16W_0402: IPN: A80345-001
R36 = RESISTOR: RES - 187 OHM 1/16W 1% 0402 SMD; AGILE_LINK: http://sj-agile9app/Agile/PLMServlet?action=OpenEmailObject&classid=10000&objid=257345545; IPN: K15740-001; Item Num: P02-14348R; LIFECYCLE_PHASE: Active; Lead Free Status: Lead Free; MFR_LIFECYCLE: Active; Manufacturer: Panasonic; Manufacturer Part Num: ERJ-2RKF1870X; Num Pins: 2; PART_SUBCLASS: RESISTORS; POWER: 1/16W; RoHS Compliant: RoHS Compliant; TOLERANCE: +/-1%
R37 = RESISTOR: RES 750 OHM 1/10W 1% 0402 SMD; IPN: K15863-001; Item Num: P02-17532R; Lead Free Status: No; Manufacturer: Panasonic; Manufacturer Part Num: ERJ-2RKF7500X; Num Pins: 2; Part Class: Resistors; Price: 0
R123 R174 = RES_0.003_OHM_1%_1_2W_2010: IPN: C14411-035
R196 = RESISTOR: RES - 27.4K Ohms, 1%, 1/16W, 0402; IPN: H30710-001; Item Num: P02-14112R; LIFECYCLE_PHASE: Active; MFR_LIFECYCLE: Active; Manufacturer: Panasonic; Manufacturer Part Num: ERJ-2RKF2742X; Num Pins: 2; PART_SUBCLASS: RESISTORS; POWER: 1/10W; RoHS Compliant: RoHS Compliant; TOLERANCE: +/-1%
R71 R197 R237 R243 R250 R342 R343 R348 = RESISTOR: RES,10.0K OHMS,1.0%,1/16W, 0402; AGILE_LINK: http://sj-agile9app/Agile/PLMServlet?action=OpenEmailObject&classid=10000&objid=146548997; IPN: A93548-034; Item Num: P02-11364R; LIFECYCLE_PHASE: Active; Lead Free Status: No; MFR_LIFECYCLE: Active; Manufacturer: Panasonic; Manufacturer Part Num: ERJ-2RKF1002X; Num Pins: 2; PART_SUBCLASS: RESISTORS; POWER: 1/16W; RESISTANCE: 10K; RoHS Compliant: Yes; TOLERANCE: +/-1%
U1 U2 = Reg_switching,_LTC3605EUF: IPN: K15491-001
U7 = LT3022EDHC: REG - VLDO, 1A, 0.9V-10V INPUT, ADJ OUTPUT, 145MV DROPOUT, (5X3X0.75)MM 16-DFN; IPN: J12555-001; Item Num: P05-18644R; Manufacturer: Linear Technology; Manufacturer Part Num: LT3022EDHC#PBF; PART_SUBCLASS: REGULATORS; RoHS Compliant: RoHS Compliant
U39 = LTC3025-1_0: REG - LINEAR REGULATOR, 500MA, 0.9V-5.5V INPUT, 0.4V-3.6V OUTPUT, 85MV DROPOUT, 80UV NOISE, DFN-6; AGILE_LINK: http://sj-agile9app/Agile/PLMServlet?action=OpenEmailObject&classid=10000&objid=259454466; IPN: K15462-001; Item Num: P05-17783R; LIFECYCLE_PHASE: Active; Lead Free Status: Lead Free; MFR_LIFECYCLE: Active; Manufacturer: Linear Technology; Manufacturer Part Num: LTC3025EDC-1#PBF; Num Pins: 7; PART_SUBCLASS: REGULATORS; RoHS Compliant: RoHS Compliant
U43 U53 = TPS51200: REG - SINK/SOURCE DDR TERMINATION REGULATOR, SON-10; AGILE_LINK: http://sj-agile9app/Agile/PLMServlet?action=OpenEmailObject&classid=10000&objid=260378996; IPN: K15456-001; Item Num: P05-18122R; LIFECYCLE_PHASE: Active; Lead Free Status: Lead Free; MFR_LIFECYCLE: Active; Manufacturer: Texas Instruments, Inc.; Manufacturer Part Num: TPS51200DRCx; Num Pins: 11; PART_SUBCLASS: REGULATORS; RoHS Compliant: RoHS Compliant
C23 = CAP: CAP - CERM, 10PF, 5%, 50V, C0G/NP0, 0402; AGILE_LINK: http://sj-agile9app/Agile/PLMServlet?action=OpenEmailObject&classid=10000&objid=242850580; IPN: K13759-001; Item Num: P03-16652R; Manufacturer: Murata; Manufacturer Part Num: GRM1555C1H100JZ01D; Num Pins: 2; PART_SUBCLASS: CAPACITORS; RATED_VOLTAGE: 50V; TOLERANCE: 5%; Working Voltage: 50V
C28 = Cap_100PF_5%_50VDC_0402: CAP - CERAMIC, 220PF, 10%, 50V, 0402, X7R; IPN: A36096-002; Item Num: P03-15090R; Manufacturer: Panasonic; Manufacturer Part Num: ECJ-0EB1H221K
J17 = CON6A: CONN - 2x3 HEADER, 2MM SMD; IPN: #N/A; Item Num: P23-38353R; LIFECYCLE_PHASE: Active; Lead Free Status: Lead Free; MFR_LIFECYCLE: Active; Manufacturer: Samtec; Manufacturer Part Num: TMM-103-01-G-D-SM; Num Pins: 6; PART_SUBCLASS: CONNECTOR; RoHS Compliant: RoHS Compliant
R1 = RESISTOR: RES - 14.7K OHM, 1/16W, 1%, 0402 SMD; IPN: E57868-001; Item Num: P02-17486R; LIFECYCLE_PHASE: Active; MFR_LIFECYCLE: Active; Manufacturer: Vishay; Manufacturer Part Num: CRCW040214K7FKED; Num Pins: 2; PART_SUBCLASS: RESISTORS; POWER: 1/16W; RoHS Compliant: RoHS Compliant; TOLERANCE: +/-1%
R5 = RESISTOR: RES - 28.7K OHM 1/16W 1% 0402 SMD; IPN: E10784-001; Item Num: P02-14387R; LIFECYCLE_PHASE: Active; MFR_LIFECYCLE: Active; Manufacturer: Vishay; Manufacturer Part Num: CRCW040228K7FKED; Num Pins: 2; PART_SUBCLASS: RESISTORS; POWER: 1/16W; RoHS Compliant: RoHS Compliant; TOLERANCE: +/-1%
R11 = RESISTOR: RES - 54.9K OHM, 1%, 1/16W 0402 SMD; IPN: K12137-001; Item Num: P02-15551R; LIFECYCLE_PHASE: Active; MFR_LIFECYCLE: Active; Manufacturer: Panasonic; Manufacturer Part Num: ERJ-2RKF5492x; Num Pins: 2; PART_SUBCLASS: RESISTORS; POWER: 1/16W; RoHS Compliant: RoHS Compliant; TOLERANCE: +/-1%
R26 = RESISTOR: RES 169K OHM 1/16W 1% 0402 SMD; IPN: A93548-290; Item Num: P02-17210R; Manufacturer: Vishay; Manufacturer Part Num: CRCW0402169KFKED
R28 = RESISTOR: RES - 31.6K OHM, 1/16W, 1%, 0402, SMD; IPN: K15717-001; Item Num: P02-14277R; LIFECYCLE_PHASE: Active; Lead Free Status: No; MFR_LIFECYCLE: Active; Manufacturer: Vishay; Manufacturer Part Num: CRCW040231K6FKED; Num Pins: 2; PART_SUBCLASS: RESISTORS; POWER: 1/16W; RoHS Compliant: Yes; TOLERANCE: +/-1%
R32 = RES_16.5K_OHM_1_10W_1%_0402: RES - 14K OHM, 1/16W, 1%, 0402, SMD; IPN: A93548-206; Item Num: P02-14278R; Manufacturer: Vishay; Manufacturer Part Num: CRCW040214K0FKED
B2 = BLANK_PART: HEAT SINK - 50MM DIAMETER, 12V FAN, THRU HOLE PCB, 22mm Push Pin ROHS COMPLIANT; IPN: K14342-001; Item Num: P12-26593R; Manufacturer: Dynatron Corporation; Manufacturer Part Num: CHR-152
C52 = CAP: CAP, CERAMIC, 10uF, 10%, X5R, 25V, 1206; IPN: C71604-002; Item Num: P03-15063R; Manufacturer: Murata; Manufacturer Part Num: GRM31CR61E106KA12; Part Class: CAPACITORS
C66 = CAP: CAP - CERAMIC, 10UF, 10%, 10VDC, 0805, X5R; Dielectric: X7R; IPN: K13557-001; Item Num: P03-15116R; Lead Free Status: No; Manufacturer: Murata; Manufacturer Part Num: GRM21BR61A106KE19L; Num Pins: 2; Part Class: Capacitors; Price: 0; RoHS Compliant: Yes; Tolerance: 20%; Working Voltage: 10V
C70 = CAP: CAP, CERAMIC, 0.1uF, 10%, 10VDC, 0402, X5R; IPN: A36096-009; Item Num: P03-15030R; LIFECYCLE_PHASE: Active; Lead Free Status: Lead Free; Manufacturer: Panasonic; Manufacturer Part Num: ECJ-0EB1A104K; Num Pins: 2; Part Class: CAPACITORS; Price: 0; RoHS Compliant: RoHS Compliant
J15 = CON2_MLX_22_23_2021: CONN, 100 mil Friction Lock Connector, Vertical, 2 pin; IPN: 641568-002; Item Num: P23-35045R; Manufacturer: Molex; Manufacturer Part Num: 22-23-2021
Q5 = PWRMOSFET_EN_GSD_0: IC, MOSFET, N-Channel, 20V; IPN: K21465-001; Item Num: P18-31002R; Manufacturer: Fairchild; Manufacturer Part Num: FDV305N_NL
R54 R67 = RESISTOR: RES ZERO OHM 1/16W 5% 0402 SMD; IPN: A93549-001; Item Num: P02-14020R; Lead Free Status: No; Manufacturer: Panasonic; Manufacturer Part Num: ERJ-2GE0R00X; Num Pins: 2; Part Class: Resistors; RoHS Compliant: Yes
R56 R57 R65 R66 = RESISTOR: RES 10K OHM 1/16W 5% 0402 SMD; IPN: D83138-001; Item Num: P02-14023R; Lead Free Status: No; Manufacturer: Panasonic; Manufacturer Part Num: ERJ-2GEJ103X; Manufacturer's Part No.: ERJ-2GEJ103X; Num Pins: 2; Part Class: RESISTORS; Price: 0; RoHS Compliant: Yes
R58 = RESISTOR: RES 383 OHM 1/16W 1% 0402 SMD; IPN: #N/A; Item Num: P02-14330R; Lead Free Status: Yes; Manufacturer: Vishay; Manufacturer Part Num: CRCW0402383RFKED; Num Pins: 2; Part Class: Resistors; Price: 0; RoHS Compliant: Yes
R232 = RESISTOR: RES - 590K OHMS,1.0%,1/10W, 0402; IPN: K15738-001; Item Num: P02-16669R; Lead Free Status: Yes; Manufacturer: Panasonic; Manufacturer Part Num: ERJ-2RKF5903x; Num Pins: 2; Part Class: Resistors; Price: 0; RoHS Compliant: Yes
R233 = RESISTOR: RES - 4.70M OHMS,1.0%,1/16W, 0402; IPN: K15737-001; Item Num: P02-16668R; Lead Free Status: No; Manufacturer: Vishay/Dale; Manufacturer Part Num: CRCW04024M70FKED; Num Pins: 2; Part Class: Resistors; Price: 0; RoHS Compliant: Yes
U42 = LT3009xDC_0: REG - LDO, 20MA, VIN 1.6V-20V, VOUT ADJ, DFN6-2X2, LT3009; IPN: K15457-001; Item Num: P05-18520R; Lead Free Status: Yes; Manufacturer: Linear Technology; Manufacturer Part Num: LT3009EDC#PBF; PART_SUBCLASS: REGULATORS; RoHS Compliant: RoHS Compliant
U45 = LTC2418: IC, ADC, 8/16 CHANNEL,24-BIT, SSOP-28; IPN: G21652-001; Item Num: P01-13149R; Lead Free Status: No; Manufacturer: Linear Technology; Manufacturer Part Num: LTC2418CGN#PBF; Num Pins: 28; Part Class: ICs; Price: 0
U48 = MAX3378_0: IC - QUAD LOW-VOLTAGE LEVEL TRANSLATOR, +/- 15KV, ESD-PROTECTED, 1UA, 16MBPS; IPN: G79250-001; Item Num: P01-13191R; Lead Free Status: Yes; Manufacturer: Maxim Integrated Products, Inc.; Manufacturer Part Num: MAX3378EEUD+; Num Pins: 14; Part Class: ICs; RoHS Compliant: Yes
V5 V6 V18 V19 V37-V44 = SENSE_PAD: IPN: #N/A

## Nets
1.1V_REG_VCC: V19.1(RSNS) ; also on sheet 24
1.5V: C29.1 C31.1 C172.1 C184.1 R196.2 U7.9(~{SHDN}) U7.12(VIN) U7.13(VIN) U7.14(VIN) U39.4(OUT) ; also on sheet 19 21
1.5V_BOOST: C144.1 D36.1 U1.20(BOOST)
1.5V_DDR3: C4.1 C25.1 C26.1 C55.1 C118.1 C152.1 C153.1 L2.2 R8.2 R174.1 R250.1 R343.1 U1.9(VON) U43.2(VLDOIN) U53.2(VLDOIN) V42.1(RSNS) ; also on sheet 12 13 14
1.5V_FB: C4.2 R8.1 R9.1 U1.4(FB)
1.5V_INTVCC: C10.1 C11.2 D36.2 R7.1 U1.2(PHMODE) U1.3(MODE) U1.21(INTVCC)
1.5V_ITH: C3.2 R4.2 R7.2 U1.6(ITH)
1.5V_RT: R10.1 U1.1(RT)
1.5V_RUN: R2.2 R3.2 U1.7(RUN)
1.5V_SS: C2.2 U1.5(TRACK/SS)
1.5V_SVIN: C143.2 R15.1 U1.19(SVIN)
1.5V_SW: C144.2 L2.1 U1.11(SW) U1.12(SW) U1.13(SW) U1.14(SW) U1.15(SW) U1.16(SW)
1.8V: V38.1(RSNS) ; also on sheet 8 14 15 19 20 21 26
2.5V: C83.1 R71.2 U48.1(VL) V5.1(RSNS) ; also on sheet 3 8 10 11 15 17 19 20 22 26
3.3V: C51.1 C119.1 C204.1 R3.1 R6.1 R30.1 R33.1 R237.2 R342.2 U39.3(IN) U43.7(EN) U43.10(VIN) U53.7(EN) U53.10(VIN) ; also on sheet 8 14 16 18 19 20 21 23 24 25 26
5.0V: C78.1 C82.1 C203.1 R56.2 R57.2 R65.2 R66.2 U39.1(BIAS) U39.6(~{SHDN}) U48.14(VCC) ; also on sheet 20 23 26
5.37V_MONITOR: C57.2 C66.1 C70.1 R54.1 R233.2 U42.2(OUT1) U42.3(OUT2) U45.9(VCC)
12V: C5.1 C21.1 C52.1 C138.1 C151.1 J15.1 R15.2 R16.2 U1.17(PVIN) U1.18(PVIN) U2.17(PVIN) U2.18(PVIN) U42.4(~{SHDN}) U42.5(VIN) ; also on sheet 18 23 24 25 26
DVDD_1.0V_ADJ: R36.2 R37.2 U7.5(ADJ)
GND: C1.1 C2.1 C3.1 C5.2 C6.2 C7.2 C10.2 C11.1 C12.1 C14.2 C16.2 C17.2 C21.2 C23.1 C24.2 C25.2 C26.2 C27.1 C28.1 C29.2 C30.2 C31.2 C33.2 C34.2 C39.2 C40.2 C51.2 C52.2 C54.2 C55.2 C56.2 C57.1 C64.2 C66.2 C70.2 C75.2 C78.2 C82.2 C83.2 C92.2 C93.2 C102.2 C118.2 C119.2 C120.2 C136.2 C137.2 C138.2 C142.1 C143.1 C151.2 C152.2 C153.2 C162.2 C163.2 C164.2 C165.2 C166.2 C167.2 C168.2 C169.1 C170.2 C171.2 C172.2 C175.2 C176.2 C177.1 C178.1 C179.1 C180.1 C181.1 C182.1 C183.1 C184.2 C189.2 C190.2 C191.2 C192.2 C193.1 C194.1 C195.1 C196.1 C197.2 C198.1 C199.2 C200.1 C201.2 C202.2 C203.2 C204.2 C209.1 C223.2 C224.1 C226.2 C227.1 C228.1 C229.1 C230.2 C231.1 C235.2 C236.1 C237.2 C238.2 C239.1 C240.2 C241.2 C242.2 C243.2 C249.2 C251.2 C252.2 C253.1 C254.1 C255.1 C256.2 C257.2 C258.2 C259.2 C260.1 C261.1 C273.2 C274.2 C275.2 C276.2 C277.2 C278.1 C279.2 C280.1 C281.2 C282.1 C283.2 C284.1 C285.1 C286.1 C287.1 C288.2 C289.2 C290.1 C291.2 C292.2 C293.2 C295.2 C302.2 C303.2 C304.1 C305.1 C306.2 C307.1 C308.2 C309.1 C310.2 C311.1 C312.2 C313.2 C314.1 C315.1 C316.2 C317.2 C320.2 C321.2 C322.2 C323.2 C324.1 C325.1 C326.1 C327.1 C328.1 C329.1 C330.2 C331.2 C332.1 C333.2 C335.2 C337.2 C338.2 C339.1 C340.1 C341.2 C342.2 C343.2 C344.2 C347.2 C348.1 C349.2 C350.1 C351.1 C352.2 C353.2 C354.2 C355.1 C356.2 C357.1 C360.2 C367.2 C368.1 C369.2 C370.1 C371.2 C376.2 C377.2 C378.1 C379.1 C380.2 C384.2 C385.1 C386.2 C388.2 C395.2 C396.2 C397.2 C398.2 C399.1 C400.2 C401.2 C402.2 C403.2 C404.2 C405.2 C406.2 C407.2 C408.2 C409.2 C410.2 C411.2 C412.1 C425.2 C427.2 C428.2 C429.2 C430.2 C435.2 C529.2 C538.2 C539.2 C540.2 C541.2 C542.2 C543.2 Q5.2(SOURCE) R9.2 R10.2 R26.2 R27.2 R36.1 R67.2 R197.2 R232.2 R243.2 R348.2 U1.10(PGND) U1.22(SGND) U1.24(CLKIN) U1.25(PGND) U2.10(PGND) U2.22(SGND) U2.24(CLKIN) U2.25(PGND) U7.6(AGND) U7.7(AGND) U7.10(PGND) U7.11(PGND) U7.17(EP_GND) U39.2(GND) U39.7(EP_GND) U42.6(GND) U42.7(GND_TAB) U43.4(PGND) U43.8(GND) U43.11(GND_PAD) U45.10(COM) U45.15(GND) U45.19(F0) U48.7(GND) U53.4(PGND) U53.8(GND) U53.11(GND_PAD) ; also on sheet 3 4 6 7 8 9 10 11 12 13 14 15 16 17 18 19 20 21 22 23 24 25 26
VCCIO_VADJ: C6.1 C7.1 C22.1 C136.1 C137.1 L1.2 R1.1 R5.1 R11.1 R28.2 R123.1 U2.9(VON) V40.1(RSNS)
C5_2.5V: C170.1 C182.2 C183.2 C194.2 C195.2 C196.2 C198.2 C200.2 C202.1 C237.1 C239.2 C257.1 C259.1 C288.1 C328.2 C339.2 C340.2 C350.2 C376.1 C398.1 C400.1 C404.1 C407.1 C409.1 C411.1 C412.2 C427.1 C430.1 ; also on sheet 7 22 26
C5_GXB_1.2V: V44.1(RSNS) ; also on sheet 25
C5_VAR_BOOST: C141.1 D37.1 U2.20(BOOST)
C5_VAR_FB: C22.2 J17.1 J17.3 J17.5 R27.1 R28.1 U2.4(FB)
C5_VAR_INTVCC: C12.2 C16.1 D37.2 R29.1 U2.2(PHMODE) U2.3(MODE) U2.21(INTVCC)
C5_VAR_ITH: C23.2 R29.2 R32.2 U2.6(ITH)
C5_VAR_RT: R26.1 U2.1(RT)
C5_VAR_RUN: R33.2 R34.2 U2.7(RUN)
C5_VAR_SS: C27.2 U2.5(TRACK/SS)
C5_VAR_SVIN: C142.2 R16.1 U2.19(SVIN)
C5_VAR_SW: C141.2 L1.1 U2.11(SW) U2.12(SW) U2.13(SW) U2.14(SW) U2.15(SW) U2.16(SW)
C5_VCC: C39.1 C54.1 C75.1 C93.1 C223.1 C235.1 C253.2 C254.2 C255.2 C256.1 C273.1 C277.1 C278.2 C279.1 C280.2 C281.1 C282.2 C283.1 C284.2 C285.2 C305.2 C306.1 C307.2 C308.1 C309.2 C310.1 C311.2 C312.1 C313.1 C322.1 C323.1 C324.2 C325.2 C326.2 C327.2 C337.1 C347.1 C384.1 V18.1(RSNS) ; also on sheet 22 24
C5_VCC_N: U45.22(CH1) V19.2(SNS)
C5_VCC_P: U45.21(CH0) V18.2(SNS)
C5_VCCE_GXBL: C64.1 C102.1 C242.1 C243.1 C258.1 C260.2 C261.2 C286.2 C287.2 C290.2 C291.1 C292.1 C293.1 C314.2 C315.2 C316.1 C317.1 C329.2 C330.1 C332.2 C333.1 C341.1 C342.1 C343.1 C344.1 C357.2 V43.1(RSNS) ; also on sheet 7 25
C5_VCCEL_GXBL_N: U45.24(CH3) V44.2(SNS)
C5_VCCEL_GXBL_P: U45.23(CH2) V43.2(SNS)
C5_VCCIO_1.5V: C92.1 C226.1 C227.2 C228.2 C236.2 C274.1 C276.1 C302.1 C320.1 C338.1 C367.1 C368.2 C377.1 C378.2 C379.2 C380.1 C385.2 C395.1 C397.1 C399.2 C402.1 C406.1 C408.1 C410.1 C428.1 R174.2 V41.1(RSNS) ; also on sheet 22
C5_VCCIO_1.5V_N: U45.2(CH9) V42.2(SNS)
C5_VCCIO_1.5V_P: U45.1(CH8) V41.2(SNS)
C5_VCCIO_1.8V: C349.1 C396.1 V37.1(RSNS) ; also on sheet 22 26
C5_VCCIO_1.8V_N: U45.28(CH7) V38.2(SNS)
C5_VCCIO_1.8V_P: U45.27(CH6) V37.2(SNS)
C5_VCCIO_2.5V: C24.1 C40.1 C193.2 C197.1 C199.1 C201.1 C224.2 C230.1 C231.2 C238.1 C240.1 C241.1 C252.1 C304.2 C348.2 C351.2 C352.1 C353.1 C354.1 C355.2 C356.1 C370.2 C371.1 C386.1 C429.1 V6.1(RSNS) ; also on sheet 10 22 26
C5_VCCIO_2.5V_N: U45.26(CH5) V5.2(SNS)
C5_VCCIO_2.5V_P: U45.25(CH4) V6.2(SNS)
C5_VCCIO_VAR: C14.1 C17.1 C30.1 C162.1 C163.1 C164.1 C165.1 C166.1 C167.1 C168.1 C169.2 C171.1 C175.1 C176.1 C177.2 C178.2 C179.2 C180.2 C181.2 C189.1 C190.1 C191.1 C192.1 C209.2 C229.2 R123.2 V39.1(RSNS) ; also on sheet 22
C5_VCCIO_VAR_N: U45.4(CH11) V40.2(SNS)
C5_VCCIO_VAR_P: U45.3(CH10) V39.2(SNS)
C5_VCCL_GXBL: C289.1 C331.1 ; also on sheet 7 25
ENET_DVDD: C33.1 C34.1 R37.1 U7.3(VOUT) U7.4(VOUT) ; also on sheet 17
OVERTEMP: Q5.1(GATE) ; also on sheet 15
PGOOD_1.5V: R6.2 U1.8(PGOOD)
PGOOD_C5_VAR: R30.2 U2.8(PGOOD)
PGOOD_C5_VCC: R2.1 R34.1 ; also on sheet 24 25 26
SENSE5_CSn: R66.1 U45.16(CSn) U48.13(IO_VCC1)
SENSE5_SCK: R57.1 U45.18(SCK) U48.10(IO_VCC4)
SENSE5_SDI: R56.1 U45.20(SDI) U48.11(IO_VCC3)
SENSE5_SDO: R65.1 U45.17(SDO) U48.12(IO_VCC2)
SENSE_CSn: U48.2(IO_VL1) ; also on sheet 15
SENSE_SCK: U48.5(IO_VL4) ; also on sheet 15
SENSE_SDI: U48.4(IO_VL3) ; also on sheet 15
SENSE_SDO: U48.3(IO_VL2) ; also on sheet 15
TSENSE_FAN_CNTL: J15.2 Q5.3(DRAIN)
VREF_DDR3A: C369.1 C401.1 C403.1 C405.1 C529.1 U53.6(REFOUT) ; also on sheet 12 22
VREF_DDR3B: C249.1 C251.1 C275.1 C303.1 C321.1 U43.6(REFOUT) ; also on sheet 13 22
VTT_DDR3A: C539.1 C540.1 C541.1 C542.1 C543.1 U53.3(VO) U53.5(VOSNS) ; also on sheet 12
VTT_DDR3B: C335.1 C360.1 C388.1 C425.1 C435.1 U43.3(VO) U43.5(VOSNS) ; also on sheet 13
N48725053: R58.2 R67.1 U45.12(REF-)
N48725073: R54.2 R58.1 U45.11(REF+)
N54913739: R71.1 U48.8(/TS)
N126530026: C1.2 R4.1
N126531468: C28.2 R32.1
N126534038: C120.1 C538.1 R343.2 R348.1 U53.1(REFIN)
N126534042: R342.1 U53.9(PGOOD)
N126534494: R232.1 R233.1 U42.1(ADJ/NC)
N126535521: J17.2 R11.2
N126535523: J17.6 R1.2
N126535539: J17.4 R5.2
N127081031: R237.1 U43.9(PGOOD)
N127081032: C56.1 C295.1 R243.1 R250.2 U43.1(REFIN)
N127475420: R196.1 R197.1 U39.5(ADJ)

Not connected (* = marked no-connect by the designer): U1 23(CLKOUT)*; U2 23(CLKOUT)*; U7 1(NC1)* 2(NC2)* 8(NC3)* 15(NC4)* 16(NC5)*; U45 5(CH12)* 6(CH13)* 7(CH14)* 8(CH15)* 13(NC1)* 14(NC2)*; U48 6(NC1)* 9(NC2)*

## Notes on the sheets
sheet 27
- Power 5 - 1.5V, VTT_DDR3, VREF_DDR3, ENET_DVDD
- CAD Note:
  Regulator input caps
  Place near regulator controller
- Design Note:
  Prefer 0603 size cap
  25V rated voltage is sufficient
- Design Note:
  tss = Css x 0.6V/2uA
  Ramp rate ~990us
- Cad Note:
  Place output caps
  near inductor
- Design Note:
  Ith is tied to INTVCC for
  internal compensation
  CAD Note:
  Overlap R?? & R??
  pads at 1 of the pins
  Place resistor & cap
  near pin 6
- DDR3 VTT, VREF
- DDR3 VTT, VREF
sheet 28
- Power 6 - LTC3605 VAR
- CAD Note:
  Regulator input caps
  Place near regulator controller
- Design Note:
  Prefer 0603 size cap
  25V rated voltage is sufficient
- Design Note:
  tss = Css x 0.6V/2uA
  Ramp rate ~990us
- Cad Note:
  Place output caps
  near inductor
- Design Note:
  Ith is tied to INTVCC for
  internal compensation
  CAD Note:
  Overlap R?? & R??
  pads at 1 of the pins
  Place resistor & cap
  near pin 6
- C5_VCCIO_VAR Voltage
- Setting
- VCCIO HSMB SELECT
- NO JUMPER
- 2.5V
- JUMPER 1-2
- 1.8V
- JUMPER 3-4
- 1.5V
- JUMPER 5-6
- 1.2V
sheet 29
- Power 6 - Power Monitor
sheet 30
- Cyclone V GT Decoupling
